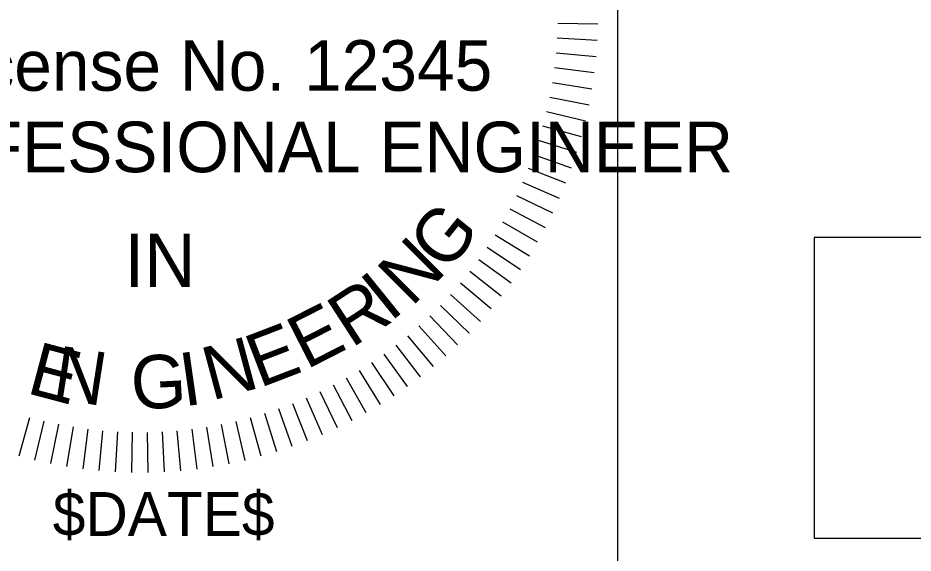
# Model space of a CAD drawing. Extents: x 0.19 to 2.82, y 0.04 to 1.79.
# Drawn here: x 2.2838 to 2.4164, y 0.7579 to 0.8372 of the extents above; entities that cross this region are included whole.
import ezdxf

# ---------------------------------------------------------------- set-up
doc = ezdxf.new("R2010")
doc.units = 0
for name, color, linetype in [('Annotation', 7, 'Continuous'), ('Seal', 7, 'Continuous'), ('Standard Info', 7, 'Continuous')]:
    doc.layers.add(name, color=color, linetype=linetype)

msp = doc.modelspace()

# ---------------------------------------------------------------- linework, layer by layer
at = {"layer": 'Seal'}
for p, q in [((2.36968, 0.83628), (2.36374, 0.83639)), ((2.36959, 0.83386), (2.36366, 0.83419)), ((2.36941, 0.83145), (2.3635, 0.83199)), ((2.36915, 0.82905), (2.36326, 0.82979)), ((2.3688, 0.82665), (2.36294, 0.82761)), ((2.36837, 0.82427), (2.36255, 0.82544)), ((2.36785, 0.82191), (2.36207, 0.82329)), ((2.36725, 0.81957), (2.36153, 0.82115)), ((2.36656, 0.81725), (2.3609, 0.81903)), ((2.3658, 0.81496), (2.3602, 0.81694)), ((2.36495, 0.8127), (2.35943, 0.81488)), ((2.36402, 0.81046), (2.35858, 0.81284)), ((2.36301, 0.80827), (2.35766, 0.81084)), ((2.36193, 0.8061), (2.35667, 0.80886)), ((2.36076, 0.80398), (2.35561, 0.80693)), ((2.35953, 0.80191), (2.35448, 0.80503)), ((2.35822, 0.79987), (2.35329, 0.80318)), ((2.35683, 0.79789), (2.35203, 0.80137)), ((2.35538, 0.79596), (2.3507, 0.79961)), ((2.35386, 0.79408), (2.34931, 0.79789)), ((2.35228, 0.79225), (2.34787, 0.79623)), ((2.35063, 0.79049), (2.34636, 0.79461)), ((2.34891, 0.78878), (2.3448, 0.79306)), ((2.34714, 0.78713), (2.34318, 0.79156)), ((2.34531, 0.78555), (2.34151, 0.79011)), ((2.34343, 0.78404), (2.33979, 0.78873)), ((2.34149, 0.78259), (2.33803, 0.78741)), ((2.3395, 0.78122), (2.33621, 0.78616)), ((2.33538, 0.77868), (2.33245, 0.78384)), ((2.33747, 0.77991), (2.33435, 0.78497)), ((2.33326, 0.77753), (2.33052, 0.78279)), ((2.3311, 0.77645), (2.32854, 0.78181)), ((2.32666, 0.77452), (2.3245, 0.78005)), ((2.3289, 0.77545), (2.32653, 0.78089)), ((2.3221, 0.77292), (2.32033, 0.77859)), ((2.32439, 0.77368), (2.32243, 0.77928)), ((2.28394, 0.7723), (2.28552, 0.77802)), ((2.28628, 0.7717), (2.28766, 0.77747)), ((2.31743, 0.77165), (2.31608, 0.77743)), ((2.31978, 0.77225), (2.31822, 0.77797)), ((2.28864, 0.77118), (2.28981, 0.777)), ((2.29102, 0.77075), (2.29198, 0.77661)), ((2.29342, 0.7704), (2.29416, 0.77629)), ((2.29582, 0.77014), (2.29636, 0.77605)), ((2.29823, 0.76996), (2.29856, 0.77589)), ((2.30548, 0.76995), (2.30517, 0.77588)), ((2.30789, 0.77012), (2.30737, 0.77603)), ((2.3103, 0.77037), (2.30957, 0.77627)), ((2.31269, 0.77072), (2.31175, 0.77658)), ((2.31507, 0.77114), (2.31392, 0.77696)), ((2.30065, 0.76987), (2.30076, 0.77581)), ((2.30306, 0.76987), (2.30297, 0.7758))]:
    msp.add_line(p, q, dxfattribs=at)
at = {"layer": 'Standard Info'}
msp.add_line((2.40174, 0.76014), (2.65457, 0.76014), dxfattribs=at)
for points in [[(2.21319, 0.49428), (2.37266, 0.49428), (2.37266, 0.91754), (2.21319, 0.91754)], [(2.40174, 0.76014), (2.65457, 0.76014), (2.65457, 0.80465), (2.40174, 0.80465)]]:
    msp.add_lwpolyline(points, close=True, dxfattribs=at)

# ---------------------------------------------------------------- texts
at = {"layer": 'Annotation'}
msp.add_text('$DATE$', height=0.0065, dxfattribs=at).set_placement((2.28893, 0.76045))
at = {"layer": 'Seal'}
for s, height, p in [('License No. 12345', 0.0075, (2.2704, 0.82641)), ('PROFESSIONAL ENGINEER', 0.0075, (2.25651, 0.81434)), ('IN', 0.0079, (2.29952, 0.79735))]:
    msp.add_text(s, height=height, dxfattribs=at).set_placement(p)
for s, rotation, p in [('G', 51.0008, (2.34728, 0.79935)), ('N', 45.0007, (2.34207, 0.79429)), ('I', 39.0007, (2.33892, 0.79207)), ('R', 33.0007, (2.33319, 0.78822)), ('E', 27.0007, (2.32648, 0.78505)), ('E', 21.0007, (2.31957, 0.78234)), ('N', 15.0007, (2.31243, 0.78049)), ('E', 345.1234, (2.28486, 0.78166)), ('N', 171.1218, (2.29743, 0.78751)), ('G', 3.0006, (2.30069, 0.77916)), ('I', 8.073, (2.30834, 0.77963))]:
    msp.add_text(s, height=0.0079, rotation=rotation, dxfattribs=at).set_placement(p)

doc.saveas('drawing.dxf')
